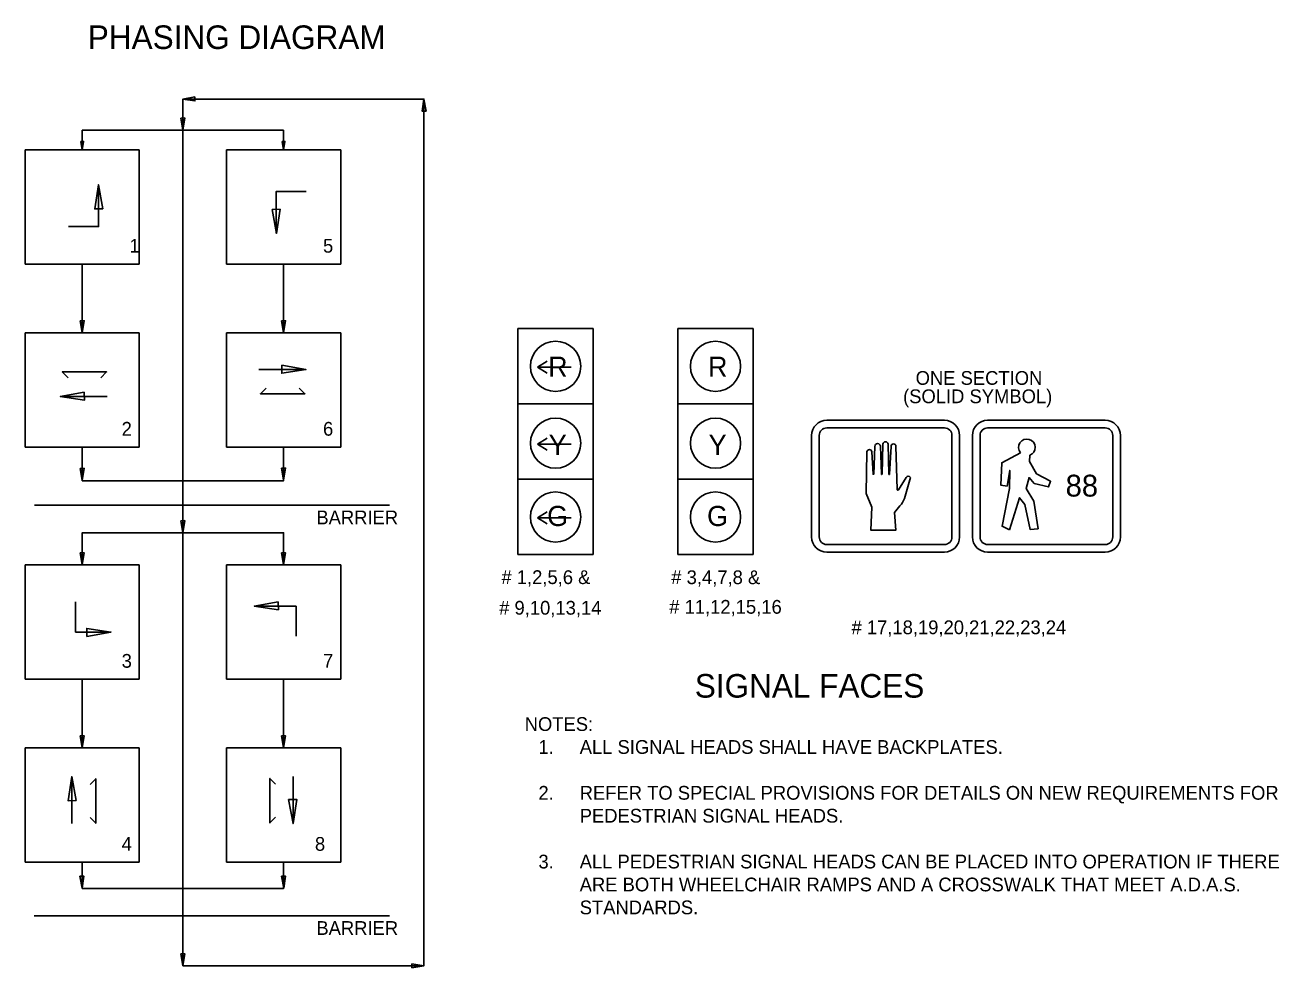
# Model space of a CAD drawing. Extents: x -19.5 to 29.5, y 0.4 to 10.6.
# Drawn here: x -12.32 to -5.02, y 4.95 to 10.44 of the extents above; entities that cross this region are included whole.
import ezdxf

# ---------------------------------------------------------------- set-up
doc = ezdxf.new("R2010")
doc.units = 0
for name, color, linetype in [('$', 7, 'Continuous'), ('PHASE', 7, 'Continuous'), ('TBLBDR', 7, 'Continuous'), ('TBLTEXT', 7, 'Continuous'), ('TITEXT', 7, 'Continuous')]:
    doc.layers.add(name, color=color, linetype=linetype)

msp = doc.modelspace()

# ---------------------------------------------------------------- linework, layer by layer
at = {"layer": '$'}
for p, q in [((-11.9837, 9.8291), (-10.8121, 9.8291)), ((-10.6825, 8.4354), (-10.9556, 8.4354)), ((-12.1114, 8.2782), (-11.8383, 8.2782)), ((-12.0217, 7.0835), (-12.0217, 6.9084)), ((-10.983, 7.0594), (-10.7397, 7.0594)), ((-10.7397, 6.8849), (-10.7397, 7.0594)), ((-12.0217, 6.9084), (-11.8167, 6.9084)), ((-11.9837, 5.5699), (-11.9837, 5.417))]:
    msp.add_line(p, q, dxfattribs=at)
for points in [[(-9.996, 10.0092), (-11.3979, 10.0092), (-11.3979, 9.8291)], [(-11.3979, 5.455), (-11.3979, 4.9667), (-9.996, 4.9667), (-9.996, 10.0092)], [(-11.9837, 9.7142), (-11.9837, 9.8291)], [(-10.8121, 9.8291), (-10.8121, 9.7142)], [(-11.888, 9.5105), (-11.888, 9.2673), (-12.0625, 9.2673)], [(-10.8546, 9.2287), (-10.8546, 9.472), (-10.6801, 9.472)], [(-11.9837, 8.6494), (-11.9837, 9.0497)], [(-10.8121, 9.0497), (-10.8121, 8.6494)], [(-10.8121, 7.9849), (-10.8121, 7.7889), (-11.9837, 7.7889), (-11.9837, 7.9849)], [(-11.3979, 7.7889), (-11.3979, 7.4864)], [(-11.9837, 7.2992), (-11.9837, 7.4864), (-10.8121, 7.4864), (-10.8121, 7.2992)], [(-11.9837, 6.2343), (-11.9837, 6.6347)], [(-10.8121, 6.6347), (-10.8121, 6.2343)], [(-12.0445, 6.0672), (-12.0445, 5.7941)], [(-10.7569, 5.7941), (-10.7569, 6.0672)]]:
    msp.add_lwpolyline(points, dxfattribs=at)
at = {"layer": 'PHASE'}
for p, q in [((-9.3354, 8.4493), (-9.2792, 8.4848)), ((-9.1402, 8.4493), (-9.3354, 8.4493)), ((-9.3354, 8.4493), (-9.2792, 8.4138)), ((-9.3354, 8.002), (-9.2792, 8.0375)), ((-9.1402, 8.002), (-9.3354, 8.002)), ((-9.3354, 8.002), (-9.2792, 7.9666)), ((-9.3354, 7.5726), (-9.2792, 7.6081)), ((-9.1402, 7.5726), (-9.3354, 7.5726)), ((-9.3354, 7.5726), (-9.2792, 7.5372))]:
    msp.add_line(p, q, dxfattribs=at)
for points in [[(-7.2269, 7.6428), (-7.2584, 7.6039), (-7.2505, 7.5014), (-7.3963, 7.5014), (-7.3911, 7.6354), (-7.4239, 7.7143), (-7.4187, 7.9567)], [(-7.3906, 7.957), (-7.3833, 7.8277)], [(-7.3792, 7.8278), (-7.3735, 7.9889)], [(-7.3391, 7.99), (-7.3346, 7.8277)], [(-7.3302, 7.8279), (-7.3257, 8.0022)], [(-7.2953, 8.0025), (-7.2913, 7.8271)], [(-7.2871, 7.8271), (-7.2785, 7.989)], [(-7.2497, 7.99), (-7.2435, 7.7384)], [(-6.5886, 7.5041), (-6.6323, 7.5237), (-6.5901, 7.7439), (-6.5884, 7.8491), (-6.6038, 7.758), (-6.6403, 7.7636), (-6.6341, 7.8934), (-6.526, 7.9521)], [(-6.4718, 7.937), (-6.4727, 7.9006), (-6.432, 7.8297), (-6.3502, 7.7854), (-6.3621, 7.7526), (-6.4458, 7.7737), (-6.4752, 7.8068), (-6.493, 7.7443), (-6.4475, 7.6696), (-6.4236, 7.5091), (-6.47, 7.5054), (-6.5005, 7.6506), (-6.5305, 7.6901), (-6.5886, 7.5041)], [(-7.2359, 7.7358), (-7.1909, 7.8079)], [(-7.165, 7.8085), (-7.2008, 7.6856)]]:
    msp.add_lwpolyline(points, dxfattribs=at)
for centre in [(-9.2299, 8.4548), (-8.2997, 8.4548), (-9.2299, 8.0075), (-8.2997, 8.0075), (-9.2299, 7.5781), (-8.2997, 7.5781)]:
    msp.add_circle(centre, 0.1461, dxfattribs=at)
for centre, radius, start, end in [((-6.4882, 7.9827), 0.0486, 289.8249, 219.00652), ((-7.4046, 7.9562), 0.0141, 3.29515, 178.19589), ((-7.3562, 7.9872), 0.0174, 9.19884, 174.46931), ((-7.3105, 8.0007), 0.0153, 6.92087, 174.32546), ((-7.2641, 7.9887), 0.0144, 5.08526, 179.16231), ((-7.3813, 7.8278), 0.00202, 181.1546, 359.79185), ((-7.3324, 7.8278), 0.00218, 181.28856, 2.11272), ((-7.2892, 7.8273), 0.00211, 183.88454, 355.84434), ((-7.1777, 7.7983), 0.0164, 38.81604, 143.75147), ((-7.2391, 7.7387), 0.00439, 183.95836, 317.86458), ((-7.2918, 7.7116), 0.0946, 313.34065, 344.09332)]:
    msp.add_arc(centre, radius, start, end, dxfattribs=at)
at = {"layer": 'TBLBDR'}
for p, q in [((-12.3159, 9.7142), (-11.6514, 9.7142)), ((-12.3159, 9.0497), (-12.3159, 9.7142)), ((-11.6514, 9.7142), (-11.6514, 9.0497)), ((-11.1444, 9.7142), (-10.4799, 9.7142)), ((-11.1444, 9.0497), (-11.1444, 9.7142)), ((-10.4799, 9.7142), (-10.4799, 9.0497)), ((-12.3159, 9.0497), (-11.6514, 9.0497)), ((-11.1444, 9.0497), (-10.4799, 9.0497)), ((-12.3159, 8.6494), (-11.6514, 8.6494)), ((-12.3159, 7.9849), (-12.3159, 8.6494)), ((-11.6514, 8.6494), (-11.6514, 7.9849)), ((-11.1444, 7.9849), (-11.1444, 8.6494)), ((-11.1444, 8.6494), (-10.4799, 8.6494)), ((-10.4799, 8.6494), (-10.4799, 7.9849)), ((-9.4491, 8.6739), (-9.0107, 8.6739)), ((-9.4491, 8.6739), (-9.4491, 7.3589)), ((-9.0107, 7.3589), (-9.0107, 8.6739)), ((-8.5189, 8.6739), (-8.0805, 8.6739)), ((-8.5189, 7.3589), (-8.5189, 8.6739)), ((-8.0805, 7.3589), (-8.0805, 8.6739)), ((-9.4491, 8.2356), (-9.0107, 8.2356)), ((-8.5189, 8.2356), (-8.0805, 8.2356)), ((-12.3159, 7.9849), (-11.6514, 7.9849)), ((-11.1444, 7.9849), (-10.4799, 7.9849)), ((-9.4491, 7.7973), (-9.0107, 7.7973)), ((-8.5189, 7.7973), (-8.0805, 7.7973)), ((-12.3159, 7.2992), (-11.6514, 7.2992)), ((-12.3159, 6.6347), (-12.3159, 7.2992)), ((-11.6514, 7.2992), (-11.6514, 6.6347)), ((-11.1444, 7.2992), (-10.4799, 7.2992)), ((-11.1444, 6.6347), (-11.1444, 7.2992)), ((-10.4799, 7.2992), (-10.4799, 6.6347)), ((-9.4491, 7.3589), (-9.0107, 7.3589)), ((-8.5189, 7.3589), (-8.0805, 7.3589)), ((-12.3159, 6.6347), (-11.6514, 6.6347)), ((-11.1444, 6.6347), (-10.4799, 6.6347)), ((-12.3159, 5.5699), (-12.3159, 6.2343)), ((-12.3159, 6.2343), (-11.6514, 6.2343)), ((-11.6514, 6.2343), (-11.6514, 5.5699)), ((-11.1444, 5.5699), (-11.1444, 6.2343)), ((-11.1444, 6.2343), (-10.4799, 6.2343)), ((-10.4799, 6.2343), (-10.4799, 5.5699)), ((-12.3159, 5.5699), (-11.6514, 5.5699)), ((-11.1444, 5.5699), (-10.4799, 5.5699))]:
    msp.add_line(p, q, dxfattribs=at)
for points in [[(-6.9682, 8.1406), (-7.6522, 8.1406)], [(-6.9682, 8.0965), (-7.6522, 8.0965)], [(-6.0327, 8.1406), (-6.7167, 8.1406)], [(-6.0327, 8.0965), (-6.7167, 8.0965)], [(-7.7403, 8.0524), (-7.7403, 7.4616)], [(-7.6963, 8.0524), (-7.6963, 7.4616)], [(-6.9242, 7.4616), (-6.9242, 8.0524)], [(-6.8801, 7.4616), (-6.8801, 8.0524)], [(-6.8048, 8.0524), (-6.8048, 7.4616)], [(-6.7607, 8.0524), (-6.7607, 7.4616)], [(-5.9886, 7.4616), (-5.9886, 8.0524)], [(-5.9446, 7.4616), (-5.9446, 8.0524)], [(-7.6522, 7.4176), (-6.9682, 7.4176)], [(-7.6522, 7.3735), (-6.9682, 7.3735)], [(-6.7167, 7.4176), (-6.0327, 7.4176)], [(-6.7167, 7.3735), (-6.0327, 7.3735)]]:
    msp.add_lwpolyline(points, dxfattribs=at)
for centre, radius, start, end in [((-7.6522, 8.0524), 0.0882, 90, 180), ((-7.6522, 8.0524), 0.0441, 90, 180), ((-6.9682, 8.0524), 0.0882, 360, 90), ((-6.9682, 8.0524), 0.0441, 360, 90), ((-6.7167, 8.0524), 0.0882, 90, 180), ((-6.7167, 8.0524), 0.0441, 90, 180), ((-6.0327, 8.0524), 0.0882, 360, 90), ((-6.0327, 8.0524), 0.0441, 360, 90), ((-7.6522, 7.4616), 0.0882, 180, 270), ((-7.6522, 7.4616), 0.0441, 180, 270), ((-6.9682, 7.4616), 0.0882, 270, 360), ((-6.9682, 7.4616), 0.0441, 270, 360), ((-6.7167, 7.4616), 0.0882, 180, 270), ((-6.7167, 7.4616), 0.0441, 180, 270), ((-6.0327, 7.4616), 0.0882, 270, 360), ((-6.0327, 7.4616), 0.0441, 270, 360)]:
    msp.add_arc(centre, radius, start, end, dxfattribs=at)
at = {"layer": 'TITEXT'}
for p, q in [((-12.2612, 7.6472), (-10.1953, 7.6472)), ((-10.8121, 5.5699), (-10.8121, 5.417)), ((-11.9837, 5.417), (-10.8121, 5.417)), ((-10.1953, 5.2584), (-12.2632, 5.2584))]:
    msp.add_line(p, q, dxfattribs=at)
for points in [[(-11.3281, 10.0221), (-11.3277, 9.9988), (-11.3979, 10.0092)], [(-9.9831, 9.9394), (-10.0064, 9.939), (-9.996, 10.0092)], [(-11.4108, 9.8989), (-11.3875, 9.8993), (-11.3979, 9.8291)], [(-11.9918, 9.7632), (-11.9755, 9.7632), (-11.9837, 9.7142)], [(-10.8203, 9.7632), (-10.804, 9.7632), (-10.8121, 9.7142)], [(-11.8639, 9.3714), (-11.9106, 9.3706), (-11.8897, 9.511)], [(-10.8788, 9.3678), (-10.8321, 9.3687), (-10.853, 9.2282)], [(-11.9953, 8.7194), (-11.972, 8.7194), (-11.9837, 8.6494)], [(-10.8238, 8.7194), (-10.8005, 8.7194), (-10.8121, 8.6494)], [(-10.8221, 8.4612), (-10.8229, 8.4146), (-10.6825, 8.4354)], [(-11.9718, 8.304), (-11.971, 8.2573), (-12.1114, 8.2782)], [(-11.9953, 7.8605), (-11.972, 7.8605), (-11.9837, 7.7905)], [(-10.8238, 7.8621), (-10.8005, 7.8621), (-10.8121, 7.7921)], [(-11.4107, 7.5562), (-11.3874, 7.5566), (-11.3978, 7.4864)], [(-11.9953, 7.3692), (-11.972, 7.3692), (-11.9837, 7.2992)], [(-10.8238, 7.3692), (-10.8005, 7.3692), (-10.8121, 7.2992)], [(-10.8434, 7.0852), (-10.8425, 7.0385), (-10.983, 7.0594)], [(-11.9564, 6.8826), (-11.9572, 6.9293), (-11.8167, 6.9084)], [(-11.9953, 6.3044), (-11.972, 6.3044), (-11.9837, 6.2343)], [(-10.8238, 6.3044), (-10.8005, 6.3044), (-10.8121, 6.2343)], [(-12.0187, 5.9276), (-12.0654, 5.9267), (-12.0445, 6.0672)], [(-10.7827, 5.9337), (-10.736, 5.9345), (-10.7569, 5.7941)], [(-11.9966, 5.4876), (-11.9732, 5.488), (-11.9837, 5.4178)], [(-10.8238, 5.4876), (-10.8005, 5.488), (-10.8109, 5.4178)], [(-11.4108, 5.0365), (-11.3875, 5.0369), (-11.3979, 4.9667)], [(-10.0657, 4.9544), (-10.0661, 4.9778), (-9.9959, 4.9674)]]:
    msp.add_lwpolyline(points, close=True, dxfattribs=at)
for points in [[(-11.3979, 9.8291), (-11.3979, 7.7889)], [(-12.0662, 8.388), (-12.0998, 8.4217), (-11.8413, 8.4217), (-11.875, 8.388)], [(-10.9134, 8.3283), (-10.947, 8.2947), (-10.6885, 8.2947), (-10.7222, 8.3283)], [(-11.3979, 7.4864), (-11.3979, 5.455)], [(-11.9381, 6.0211), (-11.9045, 6.0548), (-11.9045, 5.7963), (-11.9381, 5.8299)], [(-10.8584, 5.8321), (-10.892, 5.7985), (-10.892, 6.057), (-10.8584, 6.0234)]]:
    msp.add_lwpolyline(points, dxfattribs=at)

# ---------------------------------------------------------------- texts
at = {"layer": '$'}
for s, p in [('PHASING DIAGRAM', (-11.951, 10.3007)), ('SIGNAL FACES', (-8.4201, 6.5271))]:
    msp.add_text(s, height=0.137143, dxfattribs=at).set_placement(p)
at = {"layer": 'TBLTEXT'}
for s, height, p in [('1', 0.08, (-11.7086, 9.1158)), ('5', 0.08, (-10.5827, 9.1158)), ('R', 0.1169, (-9.2733, 8.3938)), ('R', 0.1169, (-8.343, 8.3938)), ('ONE SECTION', 0.08, (-7.1355, 8.3468)), ('(SOLID SYMBOL)', 0.08, (-7.2086, 8.2401)), ('2', 0.08, (-11.7542, 8.051)), ('6', 0.08, (-10.5827, 8.051)), ('Y', 0.1169, (-9.2697, 7.9392)), ('Y', 0.1169, (-8.3395, 7.9392)), ('88', 0.12694, (-6.263, 7.6968)), ('BARRIER', 0.08, (-10.6213, 7.5353)), ('G', 0.1169, (-9.279, 7.5254)), ('G', 0.1169, (-8.3488, 7.5254)), ('# 1,2,5,6 &', 0.08, (-9.5448, 7.1878)), ('# 3,4,7,8 &', 0.08, (-8.5569, 7.1873)), ('# 9,10,13,14', 0.08, (-9.5581, 7.0097)), ('# 11,12,15,16', 0.08, (-8.5687, 7.0152)), ('# 17,18,19,20,21,22,23,24', 0.08, (-7.5085, 6.8961)), ('3', 0.08, (-11.7542, 6.7008)), ('7', 0.08, (-10.5827, 6.7008)), ('NOTES:', 0.08, (-9.4096, 6.3332)), ('1.', 0.08, (-9.3296, 6.1999)), ('ALL SIGNAL HEADS SHALL HAVE BACKPLATES.', 0.08, (-9.0896, 6.1999)), ('2.', 0.08, (-9.3296, 5.9332)), ('REFER TO SPECIAL PROVISIONS FOR DETAILS ON NEW REQUIREMENTS FOR', 0.08, (-9.0896, 5.9332)), ('PEDESTRIAN SIGNAL HEADS.', 0.08, (-9.0896, 5.7999)), ('4', 0.08, (-11.7542, 5.636)), ('8', 0.08, (-10.6298, 5.636)), ('3.', 0.08, (-9.3296, 5.5332)), ('ALL PEDESTRIAN SIGNAL HEADS CAN BE PLACED INTO OPERATION IF THERE', 0.08, (-9.0896, 5.5332)), ('ARE BOTH WHEELCHAIR RAMPS AND A CROSSWALK THAT MEET A.D.A.S.', 0.08, (-9.0896, 5.3999)), ('STANDARDS.', 0.08, (-9.0896, 5.2665)), ('BARRIER', 0.08, (-10.6213, 5.1466))]:
    msp.add_text(s, height=height, dxfattribs=at).set_placement(p)

doc.saveas('drawing.dxf')
